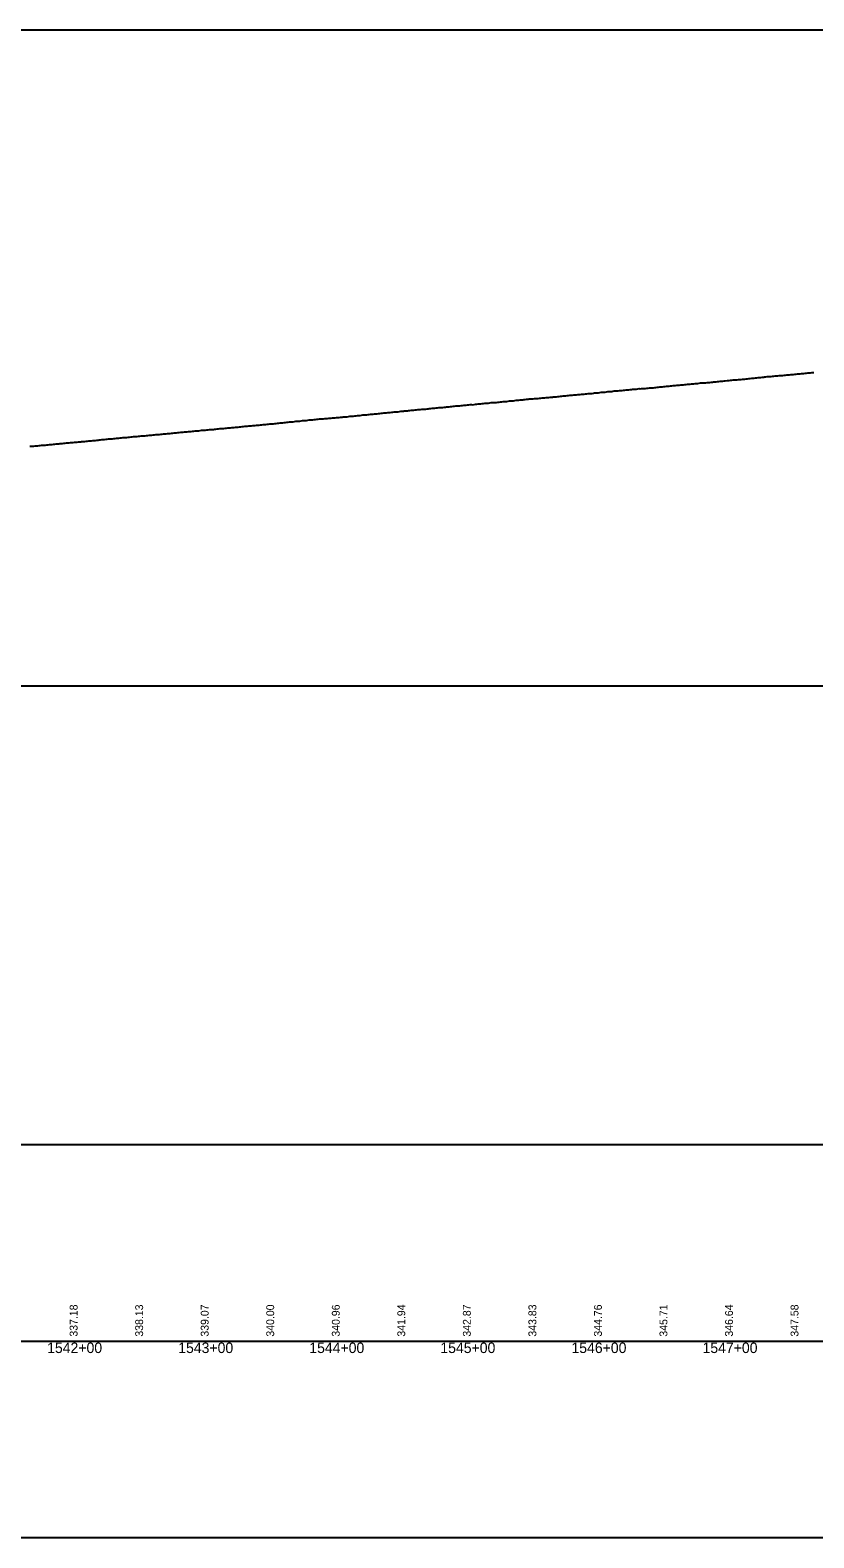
# Model space of a CAD drawing. Extents: x 2898 to 49495, y -15038 to -13538.
# Drawn here: x 43716 to 44314, y -15038 to -13888 of the extents above; entities that cross this region are included whole.
import ezdxf

# ---------------------------------------------------------------- set-up
doc = ezdxf.new("R2010")
doc.units = 0
for name, color, linetype in [('RD_DDB_Profile_EX', 7, 'Continuous'), ('RD_DDB_StaTX', 7, 'Continuous'), ('RD_DDB_StripGrade', 7, 'Continuous'), ('RD_GPK_Profile_Cell', 7, 'Continuous'), ('RD_SHT_ShtClip', 7, 'Continuous')]:
    doc.layers.add(name, color=color, linetype=linetype)

msp = doc.modelspace()

# ---------------------------------------------------------------- linework, layer by layer
at = {"layer": 'RD_DDB_Profile_EX'}
for points in [[(44165.9, -14163.4), (44166.9, -14163.3), (44167.9, -14163.2), (44168.9, -14163), (44169.9, -14163), (44170.9, -14162.9), (44172.1, -14162.8), (44172.9, -14162.7), (44173.9, -14162.6), (44174.9, -14162.5), (44175.9, -14162.4), (44176.9, -14162.3), (44177.9, -14162.3), (44178.9, -14162.2), (44179.9, -14162.1), (44180.9, -14161.9), (44181.7, -14162.1), (44182.7, -14161.9), (44183.7, -14161.9), (44184.7, -14161.8), (44185.7, -14161.7), (44186.7, -14161.6), (44187.7, -14161.5), (44188.7, -14161.4), (44189.7, -14161.3), (44190.7, -14161.2), (44191.1, -14161.2), (44191.7, -14161.2), (44192.7, -14161.1), (44193.7, -14161), (44194.7, -14160.8), (44195.7, -14160.7), (44196.7, -14160.6), (44197.7, -14160.5), (44198.7, -14160.4), (44199.7, -14160.3), (44200.7, -14160.3), (44201.7, -14160.1), (44202.7, -14160), (44203.7, -14159.9), (44204.7, -14159.8), (44205.7, -14159.7), (44206.7, -14159.6), (44207.7, -14159.5), (44208.7, -14159.4), (44209.7, -14159.3), (44210, -14159.3), (44210.7, -14159.3), (44211.7, -14159.2), (44212.7, -14159.1), (44213.7, -14159), (44214.7, -14158.9), (44215.7, -14158.8), (44216.7, -14158.7), (44217.7, -14158.6), (44218.7, -14158.5), (44219.7, -14158.5), (44220.7, -14158.3), (44221.7, -14158.2), (44222.7, -14158.2), (44223.7, -14158.1), (44224.7, -14158), (44225.7, -14157.9), (44226.7, -14157.8), (44227.7, -14157.6), (44228.9, -14157.6), (44229.7, -14157.5), (44230.7, -14157.5), (44231.7, -14157.4), (44232.7, -14157.2), (44233.7, -14157.2), (44234.7, -14157.2), (44235.7, -14156.9), (44236.7, -14156.9), (44237.6, -14156.8), (44238.6, -14156.7), (44239.6, -14156.6), (44240.6, -14156.5), (44241.6, -14156.4), (44242.6, -14156.3), (44243.6, -14156.2), (44244.6, -14156.1), (44245.6, -14155.9), (44246.6, -14155.9), (44247.9, -14155.8), (44248.6, -14155.8), (44249.6, -14155.7), (44250.6, -14155.5), (44251.6, -14155.4), (44252.6, -14155.3), (44253.6, -14155.3), (44254.6, -14155.2), (44255.6, -14155.2), (44256.6, -14155), (44257.6, -14154.9), (44258.6, -14154.9), (44259.6, -14154.7), (44260.6, -14154.6), (44261.6, -14154.6), (44262.6, -14154.4), (44263.6, -14154.3)], [(44263.6, -14154.3), (44264.6, -14154.2), (44265.6, -14154.1), (44266.8, -14154), (44267.6, -14153.9), (44268.6, -14153.8), (44269.6, -14153.7), (44270.6, -14153.6), (44271.6, -14153.5), (44272.6, -14153.5), (44273.6, -14153.4), (44274.6, -14153.2), (44275.6, -14153.2), (44276.3, -14153.1), (44276.6, -14153), (44277.6, -14152.9), (44278.6, -14152.7), (44279.6, -14152.7), (44280.6, -14152.7), (44281.6, -14152.6), (44282.6, -14152.4), (44283.6, -14152.3), (44284.6, -14152.2), (44285.8, -14152.1), (44286.6, -14152.1), (44287.6, -14152), (44288.6, -14151.9), (44289.6, -14151.9), (44290.6, -14151.8), (44291.6, -14151.7), (44292.6, -14151.5), (44293.6, -14151.4), (44294.2, -14151.3), (44294.6, -14151.3), (44295.2, -14151.3), (44295.6, -14151.3), (44296.6, -14151.1), (44297.6, -14151.1), (44298.6, -14151), (44299.6, -14150.9), (44300.6, -14150.8), (44301.6, -14150.7), (44302.6, -14150.6), (44303.6, -14150.5), (44304.7, -14150.4), (44305.6, -14150.4), (44306.6, -14150.3), (44307.6, -14150.2), (44308.6, -14150.2), (44309.6, -14149.9), (44310.6, -14149.9), (44311.6, -14149.8), (44312.6, -14149.6), (44313.6, -14149.6), (44314.2, -14149.5)], [(44069, -14172.6), (44070, -14172.5), (44071, -14172.4), (44072, -14172.4), (44073, -14172.2), (44074, -14172.1), (44075, -14172), (44076, -14171.9), (44077, -14171.8), (44077.4, -14171.8), (44078, -14171.8), (44079, -14171.6), (44079.9, -14171.6), (44080.9, -14171.4), (44081.9, -14171.3), (44082.9, -14171.2), (44084, -14171.1), (44085, -14171.1), (44086, -14170.9), (44087, -14170.8), (44088, -14170.7), (44089, -14170.6), (44090, -14170.5), (44091, -14170.4), (44092, -14170.4), (44092.9, -14170.3), (44093.9, -14170.1), (44094.9, -14170), (44095.9, -14170), (44096.3, -14169.9), (44096.9, -14169.8), (44097.9, -14169.8), (44098.9, -14169.7), (44099.9, -14169.7), (44100.9, -14169.5), (44101.9, -14169.4), (44102.9, -14169.4), (44103.9, -14169.3), (44104.9, -14169.2), (44105.9, -14169.1), (44106.9, -14169), (44107.9, -14168.9), (44109, -14168.8), (44110, -14168.7), (44111, -14168.6), (44112, -14168.6), (44112.9, -14168.4), (44113.9, -14168.4), (44114.9, -14168.3), (44115.3, -14168.2), (44115.9, -14168.2), (44116.9, -14168.1), (44117.9, -14168.1), (44118.9, -14168), (44119.9, -14168), (44120.9, -14167.7), (44121.9, -14167.6), (44122.9, -14167.5), (44123.9, -14167.4), (44124.9, -14167.3), (44125.9, -14167.2), (44126.9, -14167.1), (44127.9, -14167), (44128.9, -14166.9), (44129.9, -14166.8), (44131, -14166.7), (44132, -14166.6), (44133, -14166.6), (44134.2, -14166.3), (44135, -14166.3), (44135.9, -14166.3), (44136.9, -14166.2), (44137.9, -14166.1), (44138.9, -14166), (44139.9, -14165.9), (44140.9, -14165.8), (44141.9, -14165.7), (44142.9, -14165.6), (44143.9, -14165.5), (44144.9, -14165.5), (44145.9, -14165.4), (44146.9, -14165.2), (44147.9, -14165.2), (44148.9, -14165), (44149.9, -14165), (44150.9, -14164.9), (44151.9, -14164.7), (44153.2, -14164.7), (44153.9, -14164.6), (44154.9, -14164.5), (44155.9, -14164.3), (44156.9, -14164.2), (44157.9, -14164.2), (44158.9, -14164.1), (44159.9, -14164), (44160.9, -14163.9), (44161.9, -14163.7), (44162.9, -14163.6), (44163.9, -14163.7), (44164.9, -14163.7), (44165.9, -14163.4)], [(43973.2, -14181.8), (43974, -14181.6), (43975, -14181.6), (43976, -14181.5), (43977, -14181.4), (43978, -14181.3), (43979, -14181.1), (43980, -14181.1), (43981, -14181), (43982, -14180.9), (43983, -14180.8), (43984, -14180.7), (43985, -14180.5), (43986, -14180.4), (43987, -14180.3), (43988, -14180.3), (43989, -14180.2), (43990, -14180.1), (43991, -14180.1), (43992.1, -14179.8), (43993, -14179.8), (43994, -14179.7), (43995, -14179.6), (43996, -14179.5), (43997, -14179.5), (43998, -14179.4), (43999, -14179.2), (44000, -14179.1), (44001, -14179), (44001.6, -14178.9), (44002, -14178.9), (44003, -14178.8), (44004, -14178.8), (44005, -14178.7), (44006, -14178.5), (44007, -14178.4), (44008, -14178.3), (44009, -14178.2), (44010, -14178.1), (44011.1, -14178), (44012, -14177.9), (44013, -14177.8), (44014, -14177.7), (44015, -14177.6), (44016, -14177.6), (44017, -14177.5), (44018, -14177.5), (44019, -14177.2), (44020, -14177.2), (44020.6, -14177.1), (44021, -14177.1), (44022, -14177), (44023, -14176.9), (44024, -14176.8), (44025, -14176.7), (44026, -14176.5), (44027, -14176.5), (44028, -14176.4), (44029, -14176.3), (44030, -14176.2), (44031, -14176.2), (44032, -14176), (44033, -14176), (44034, -14175.8), (44035, -14175.7), (44036, -14175.7), (44037, -14175.5), (44038, -14175.4), (44039, -14175.3), (44039.5, -14175.3), (44040, -14175.3), (44041, -14175.1), (44042, -14175.1), (44043, -14175), (44044, -14174.9), (44045, -14174.8), (44046, -14174.7), (44047, -14174.6), (44048, -14174.5), (44049, -14174.4), (44050, -14174.3), (44051, -14174.2), (44052, -14174.1), (44053, -14174.1), (44054, -14174.2), (44055, -14173.9), (44056, -14173.8), (44057, -14173.7), (44058, -14173.6), (44058.4, -14173.5), (44059, -14173.5), (44060, -14173.4), (44061, -14173.3), (44062, -14173.2), (44063, -14173.1), (44064, -14173), (44065, -14172.9), (44066, -14172.9), (44067, -14172.7), (44068, -14172.6), (44069, -14172.6)], [(43781, -14199.9), (43782, -14199.8), (43783, -14199.7), (43784, -14199.6), (43785, -14199.5), (43786, -14199.3), (43787, -14199.2), (43788, -14199.2), (43789, -14199.1), (43790, -14199.1), (43791, -14199), (43792, -14198.9), (43793.2, -14198.7), (43794, -14198.7), (43795, -14198.5), (43796, -14198.5), (43797, -14198.4), (43798, -14198.3), (43799, -14198.2), (43800, -14198.1), (43801, -14198), (43802, -14197.9), (43803, -14197.9), (43804, -14197.8), (43805, -14197.7), (43806, -14197.6), (43807, -14197.5), (43808, -14197.4), (43809, -14197.3), (43810, -14197.2), (43811, -14197.1), (43812.2, -14197), (43813, -14197), (43814, -14196.8), (43815, -14196.8), (43816, -14196.7), (43817, -14196.6), (43818, -14196.5), (43819, -14196.4), (43820, -14196.3), (43821, -14196.2), (43821.7, -14196.2), (43822, -14196.2), (43823, -14196.1), (43824, -14195.9), (43825, -14195.8), (43826, -14195.7), (43827, -14195.6), (43828, -14195.5), (43829, -14195.4), (43830, -14195.4), (43831.1, -14195.2), (43832, -14195.1), (43833, -14195), (43834, -14194.9), (43835, -14194.9), (43836, -14194.8), (43837, -14194.6), (43838, -14194.5), (43839, -14194.5), (43840, -14194.4), (43840.6, -14194.3), (43841, -14194.3), (43842, -14194.2), (43843, -14194.1), (43844, -14194), (43845, -14194), (43846, -14193.8), (43847, -14193.7), (43848, -14193.6), (43849, -14193.5), (43850.1, -14193.5), (43851, -14193.4), (43852, -14193.3), (43853, -14193.1), (43854, -14193.1), (43855, -14193.1), (43856, -14193), (43857, -14192.8), (43858, -14192.8), (43859, -14192.6), (43859.6, -14192.5), (43860, -14192.5), (43861, -14192.4), (43862, -14192.4), (43862.4, -14192.4), (43863, -14192.3), (43864, -14192.2), (43865, -14192.1), (43866, -14192), (43867, -14191.9), (43868, -14191.8), (43869, -14191.8), (43870, -14191.6), (43871, -14191.5), (43872, -14191.5), (43873, -14191.4), (43874, -14191.2), (43875, -14191.2), (43876, -14191.1), (43877, -14191)], [(43877, -14191), (43878, -14190.9), (43878.5, -14190.8), (43879, -14190.7), (43880, -14190.6), (43881, -14190.5), (43882, -14190.5), (43883, -14190.3), (43884, -14190.3), (43885, -14190.2), (43886, -14190.1), (43887, -14190), (43888, -14189.9), (43889, -14189.8), (43890, -14189.7), (43891, -14189.7), (43892, -14189.6), (43893, -14189.5), (43894, -14189.3), (43895, -14189.3), (43896, -14189.2), (43897, -14189.1), (43897.4, -14189), (43898, -14189), (43899, -14188.8), (43900, -14188.8), (43901, -14188.7), (43902, -14188.7), (43903, -14188.5), (43904, -14188.4), (43905, -14188.3), (43906, -14188.3), (43907, -14188.1), (43908, -14188), (43909, -14187.9), (43910, -14187.8), (43911, -14187.7), (43912, -14187.6), (43913, -14187.5), (43914, -14187.3), (43915, -14187.3), (43916, -14187.2), (43916.4, -14187.1), (43917, -14187.1), (43918, -14186.9), (43919, -14186.8), (43920, -14186.8), (43921, -14186.7), (43922, -14186.7), (43923, -14186.4), (43924, -14186.3), (43925, -14186.2), (43926, -14186.1), (43927, -14186.1), (43928, -14185.9), (43929, -14185.8), (43930, -14185.7), (43931, -14185.6), (43932, -14185.6), (43933, -14185.5), (43934, -14185.4), (43935, -14185.3), (43935.3, -14185.3), (43936, -14185.2), (43937, -14185), (43938, -14185), (43939, -14185), (43940, -14184.9), (43941, -14184.8), (43942, -14184.7), (43943, -14184.6), (43944, -14184.5), (43945, -14184.5), (43946, -14184.4), (43947, -14184.2), (43948, -14184.1), (43949, -14184.1), (43950, -14184), (43951, -14183.9), (43952, -14183.8), (43953, -14183.7), (43954.3, -14183.6), (43955, -14183.5), (43956, -14183.4), (43957, -14183.4), (43958, -14183.3), (43959, -14183.1), (43960, -14183), (43961, -14183), (43962, -14182.9), (43963, -14182.8), (43964, -14182.7), (43965, -14182.6), (43966, -14182.4), (43967, -14182.4), (43968, -14182.3), (43969, -14182.2), (43970, -14182), (43971, -14182), (43972, -14182), (43973.2, -14181.8)], [(43716, -14205.9), (43717, -14205.8), (43717.5, -14205.8), (43718, -14205.7), (43719, -14205.7), (43720, -14205.6), (43721, -14205.5), (43722, -14205.4), (43723, -14205.3), (43724, -14205.2), (43725, -14205.1), (43726, -14205), (43727, -14204.9), (43728, -14204.9), (43729, -14204.8), (43730, -14204.7), (43731, -14204.5), (43732, -14204.4), (43733, -14204.4), (43734, -14204.3), (43735, -14204.2), (43736, -14204.1), (43736.4, -14204.1), (43737, -14204), (43738, -14203.9), (43739, -14203.8), (43740, -14203.7), (43741, -14203.7), (43742, -14203.6), (43743, -14203.5), (43744, -14203.3), (43745, -14203.3), (43746, -14203.2), (43747, -14203.1), (43748, -14203), (43749, -14202.9), (43750, -14202.8), (43751, -14202.8), (43752, -14202.7), (43753, -14202.6), (43754, -14202.5), (43755, -14202.4), (43755.3, -14202.3), (43756, -14202.2), (43757, -14202.2), (43758, -14202.1), (43759, -14202), (43760, -14201.9), (43761, -14201.7), (43762, -14201.7), (43763, -14201.6), (43764, -14201.5), (43765, -14201.4), (43766, -14201.4), (43767, -14201.2), (43768, -14201.1), (43769, -14201), (43770, -14201), (43771, -14200.8), (43772, -14200.7), (43773, -14200.6), (43774.3, -14200.5), (43775, -14200.5), (43776, -14200.3), (43777, -14200.2), (43778, -14200.1), (43779, -14200.1), (43780, -14200), (43781, -14199.9)]]:
    msp.add_lwpolyline(points, dxfattribs=at)
at = {"layer": 'RD_GPK_Profile_Cell'}
msp.add_line((2976.1, -14888.5), (48721.1, -14888.5), dxfattribs=at)
at = {"layer": 'RD_SHT_ShtClip'}
for points in [[(43475.4, -13888.5), (43475.4, -14388.5), (44975.4, -14388.5), (44975.4, -14388.5), (44975.4, -13888.5), (44975.4, -13888.5)], [(43455.4, -14738.5), (44995.4, -14738.5), (44995.4, -15038.5), (43455.4, -15038.5)]]:
    msp.add_lwpolyline(points, close=True, dxfattribs=at)

# ---------------------------------------------------------------- texts
at = {"layer": 'RD_DDB_StaTX'}
for s, p in [('1542+00', (43729.2, -14897.5)), ('1543+00', (43829.2, -14897.5)), ('1544+00', (43929.2, -14897.5)), ('1545+00', (44029.2, -14897.5)), ('1546+00', (44129.2, -14897.5)), ('1547+00', (44229.2, -14897.5))]:
    msp.add_text(s, height=8, dxfattribs=at).set_placement(p)
at = {"layer": 'RD_DDB_StripGrade'}
for s, p in [('337.18', (43752.4, -14885)), ('338.13', (43802.4, -14885)), ('339.07', (43852.4, -14885)), ('340.00', (43902.4, -14885)), ('340.96', (43952.4, -14885)), ('341.94', (44002.4, -14885)), ('342.87', (44052.4, -14885)), ('343.83', (44102.4, -14885)), ('344.76', (44152.4, -14885)), ('345.71', (44202.4, -14885)), ('346.64', (44252.4, -14885)), ('347.58', (44302.4, -14885))]:
    msp.add_text(s, height=6, rotation=90, dxfattribs=at).set_placement(p)

doc.saveas('drawing.dxf')
